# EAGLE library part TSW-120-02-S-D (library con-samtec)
THROUGH-HOLE .025" SQ POST HEADER Source: Samtec TSW.pdf
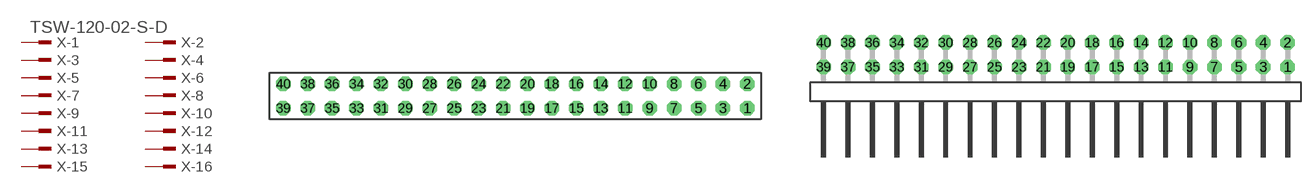
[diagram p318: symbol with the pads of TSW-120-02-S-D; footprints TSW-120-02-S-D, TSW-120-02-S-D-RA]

Designator prefix X; gates -1=MPINV -2=MPIN -3=MPIN -4=MPIN -5=MPIN -6=MPIN -7=MPIN -8=MPIN -9=MPIN -10=MPIN -11=MPIN -12=MPIN -13=MPIN -14=MPIN -15=MPIN -16=MPIN -17=MPIN -18=MPIN -19=MPIN -20=MPIN -21=MPIN -22=MPIN -23=MPIN -24=MPIN -25=MPIN -26=MPIN -27=MPIN -28=MPIN -29=MPIN -30=MPIN -31=MPIN -32=MPIN -33=MPIN -34=MPIN -35=MPIN -36=MPIN -37=MPIN -38=MPIN -39=MPIN -40=MPIN

## TSW-120-02-S-D (OC_FARNELL: unknown; OC_NEWARK: unknown)  [TSW-120-02-S-D]
1  -1:1  pas
2  -2:1  pas
3  -3:1  pas
4  -4:1  pas
5  -5:1  pas
6  -6:1  pas
7  -7:1  pas
8  -8:1  pas
9  -9:1  pas
10  -10:1  pas
11  -11:1  pas
12  -12:1  pas
13  -13:1  pas
14  -14:1  pas
15  -15:1  pas
16  -16:1  pas
17  -17:1  pas
18  -18:1  pas
19  -19:1  pas
20  -20:1  pas
21  -21:1  pas
22  -22:1  pas
23  -23:1  pas
24  -24:1  pas
25  -25:1  pas
26  -26:1  pas
27  -27:1  pas
28  -28:1  pas
29  -29:1  pas
30  -30:1  pas
31  -31:1  pas
32  -32:1  pas
33  -33:1  pas
34  -34:1  pas
35  -35:1  pas
36  -36:1  pas
37  -37:1  pas
38  -38:1  pas
39  -39:1  pas
40  -40:1  pas

## TSW-120-02-S-D-RA (OC_FARNELL: unknown; OC_NEWARK: unknown)  [TSW-120-02-S-D-RA]
Pads as for TSW-120-02-S-D

## Footprint TSW-120-02-S-D (pad centres in mm)
THROUGH-HOLE .025" SQ POST HEADER Source: Samtec TSW.pdf
drill 1 pad 1.5 octagon: 1 24.13,-1.27; 2 24.13,1.27; 3 21.59,-1.27; 4 21.59,1.27; 5 19.05,-1.27; 6 19.05,1.27; 7 16.51,-1.27; 8 16.51,1.27; 9 13.97,-1.27; 10 13.97,1.27; 11 11.43,-1.27; 12 11.43,1.27; 13 8.89,-1.27; 14 8.89,1.27; 15 6.35,-1.27; 16 6.35,1.27; 17 3.81,-1.27; 18 3.81,1.27; 19 1.27,-1.27; 20 1.27,1.27; 21 -1.27,-1.27; 22 -1.27,1.27; 23 -3.81,-1.27; 24 -3.81,1.27; 25 -6.35,-1.27; 26 -6.35,1.27; 27 -8.89,-1.27; 28 -8.89,1.27; 29 -11.43,-1.27; 30 -11.43,1.27; 31 -13.97,-1.27; 32 -13.97,1.27; 33 -16.51,-1.27; 34 -16.51,1.27; 35 -19.05,-1.27; 36 -19.05,1.27; 37 -21.59,-1.27; 38 -21.59,1.27; 39 -24.13,-1.27; 40 -24.13,1.27

## Footprint TSW-120-02-S-D-RA (pad centres in mm)
THROUGH-HOLE .025" SQ POST HEADER Source: Samtec TSW.pdf
drill 1 pad 1.5 octagon: 1 24.13,1.524; 2 24.13,4.064; 3 21.59,1.524; 4 21.59,4.064; 5 19.05,1.524; 6 19.05,4.064; 7 16.51,1.524; 8 16.51,4.064; 9 13.97,1.524; 10 13.97,4.064; 11 11.43,1.524; 12 11.43,4.064; 13 8.89,1.524; 14 8.89,4.064; 15 6.35,1.524; 16 6.35,4.064; 17 3.81,1.524; 18 3.81,4.064; 19 1.27,1.524; 20 1.27,4.064; 21 -1.27,1.524; 22 -1.27,4.064; 23 -3.81,1.524; 24 -3.81,4.064; 25 -6.35,1.524; 26 -6.35,4.064; 27 -8.89,1.524; 28 -8.89,4.064; 29 -11.43,1.524; 30 -11.43,4.064; 31 -13.97,1.524; 32 -13.97,4.064; 33 -16.51,1.524; 34 -16.51,4.064; 35 -19.05,1.524; 36 -19.05,4.064; 37 -21.59,1.524; 38 -21.59,4.064; 39 -24.13,1.524; 40 -24.13,4.064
